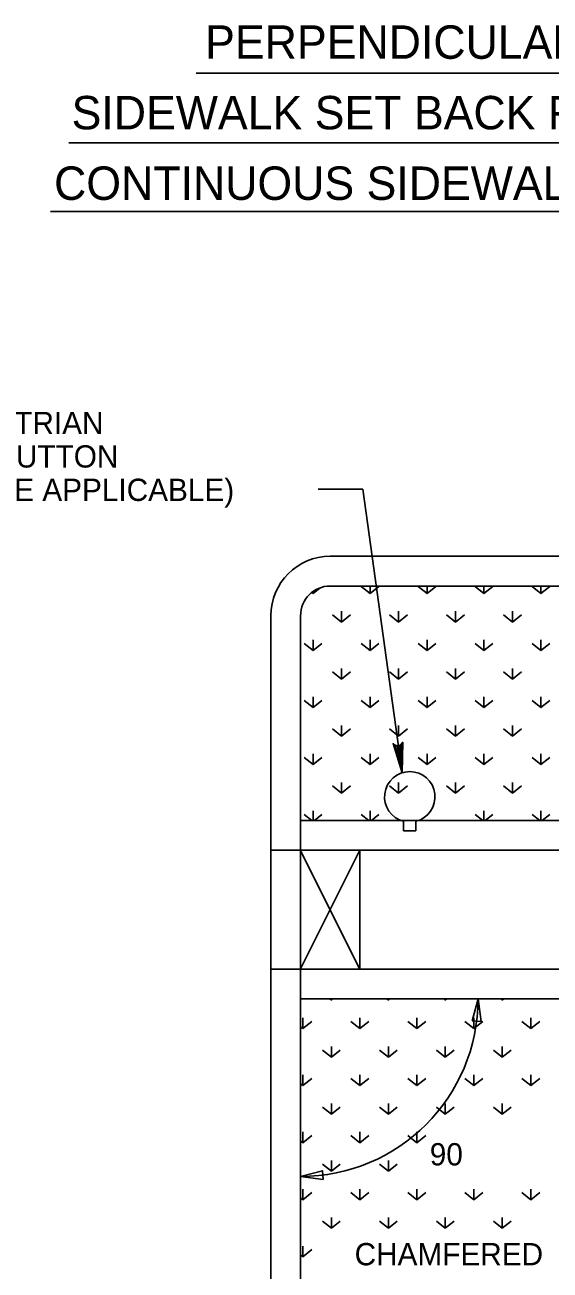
# Model space of a CAD drawing. Extents: x -344 to 940, y 22 to 1233.
# Drawn here: x 411 to 481.8, y 128.6 to 296.2 of the extents above; entities that cross this region are included whole.
import ezdxf

# ---------------------------------------------------------------- set-up
doc = ezdxf.new("R2010")
doc.units = 0
doc.layers.add('2', color=7, linetype='Continuous')
doc.layers.add('Default', color=7, linetype='Continuous')

msp = doc.modelspace()

# ---------------------------------------------------------------- linework, layer by layer
at = {"layer": '2'}
for p, q in [((434.15, 289.75), (543.1, 289.75)), ((416.96, 280.34), (561.11, 280.34)), ((414.51, 271.13), (563.16, 271.13)), ((462.1, 187.7), (462.1, 189)), ((463.75, 189), (463.75, 187.7)), ((463.75, 187.7), (462.1, 187.7)), ((456.2, 185.09), (448.14, 169.03)), ((448.19, 185.04), (456.2, 169.09))]:
    msp.add_line(p, q, dxfattribs=at)
msp.add_lwpolyline([(461.83, 199.42), (461.57, 199.24), (461.88, 195.53), (461.83, 199.42), (461.97, 199.64), (461.88, 195.53), (461.19, 199.18), (460.89, 199.28), (461.88, 195.53), (460.68, 199.46), (460.89, 199.28)], dxfattribs=at)
msp.add_arc((462.93, 192.29), 3.4, 284.1014, 255.8986, dxfattribs=at)
at = {"layer": 'Default'}
for p, q in [((456.6, 233.73), (450.6, 233.73)), ((461.88, 195.53), (456.6, 233.73)), ((452.2, 224.68), (656.79, 224.68)), ((449.89, 219.67), (449.76, 219.77)), ((449.89, 219.67), (450.82, 220.41)), ((449.89, 219.86), (449.89, 219.67)), ((452.2, 220.68), (656.79, 220.68)), ((457.57, 219.67), (456.37, 220.63)), ((457.57, 220.68), (457.57, 219.67)), ((457.57, 219.67), (458.77, 220.63)), ((465.25, 219.67), (464.05, 220.63)), ((465.25, 220.68), (465.25, 219.67)), ((465.25, 219.67), (466.45, 220.63)), ((472.93, 219.67), (471.73, 220.63)), ((472.93, 220.68), (472.93, 219.67)), ((472.93, 219.67), (474.13, 220.63)), ((480.61, 219.67), (479.41, 220.63)), ((480.61, 220.68), (480.61, 219.67)), ((480.61, 219.67), (481.81, 220.63)), ((444.2, 216.68), (444.2, 193.09)), ((448.2, 216.68), (448.2, 169.09)), ((453.73, 215.83), (452.53, 216.79)), ((453.73, 217.27), (453.73, 215.83)), ((453.73, 215.83), (454.93, 216.79)), ((461.41, 215.83), (460.21, 216.79)), ((461.41, 217.27), (461.41, 215.83)), ((461.41, 215.83), (462.61, 216.79)), ((469.09, 215.83), (467.89, 216.79)), ((469.09, 217.27), (469.09, 215.83)), ((469.09, 215.83), (470.29, 216.79)), ((476.77, 215.83), (475.57, 216.79)), ((476.77, 217.27), (476.77, 215.83)), ((476.77, 215.83), (477.97, 216.79)), ((449.89, 211.99), (448.69, 212.95)), ((449.89, 213.43), (449.89, 211.99)), ((449.89, 211.99), (451.09, 212.95)), ((457.57, 211.99), (456.37, 212.95)), ((457.57, 213.43), (457.57, 211.99)), ((457.57, 211.99), (458.77, 212.95)), ((465.25, 211.99), (464.05, 212.95)), ((465.25, 213.43), (465.25, 211.99)), ((465.25, 211.99), (466.45, 212.95)), ((472.93, 211.99), (471.73, 212.95)), ((472.93, 213.43), (472.93, 211.99)), ((472.93, 211.99), (474.13, 212.95)), ((480.61, 211.99), (479.41, 212.95)), ((480.61, 213.43), (480.61, 211.99)), ((480.61, 211.99), (481.81, 212.95)), ((453.73, 209.59), (453.73, 208.15)), ((461.41, 209.59), (461.41, 208.15)), ((469.09, 209.59), (469.09, 208.15)), ((476.77, 209.59), (476.77, 208.15)), ((453.73, 208.15), (452.53, 209.11)), ((453.73, 208.15), (454.93, 209.11)), ((461.41, 208.15), (460.21, 209.11)), ((461.41, 208.15), (462.61, 209.11)), ((469.09, 208.15), (467.89, 209.11)), ((469.09, 208.15), (470.29, 209.11)), ((476.77, 208.15), (475.57, 209.11)), ((476.77, 208.15), (477.97, 209.11)), ((449.89, 204.31), (448.69, 205.27)), ((449.89, 205.75), (449.89, 204.31)), ((449.89, 204.31), (451.09, 205.27)), ((457.57, 204.31), (456.37, 205.27)), ((457.57, 205.75), (457.57, 204.31)), ((457.57, 204.31), (458.77, 205.27)), ((465.25, 204.31), (464.05, 205.27)), ((465.25, 205.75), (465.25, 204.31)), ((465.25, 204.31), (466.45, 205.27)), ((472.93, 204.31), (471.73, 205.27)), ((472.93, 205.75), (472.93, 204.31)), ((472.93, 204.31), (474.13, 205.27)), ((480.61, 204.31), (479.41, 205.27)), ((480.61, 205.75), (480.61, 204.31)), ((480.61, 204.31), (481.81, 205.27)), ((453.73, 200.47), (452.53, 201.43)), ((453.73, 201.91), (453.73, 200.47)), ((453.73, 200.47), (454.93, 201.43)), ((461.41, 200.47), (460.21, 201.43)), ((461.41, 201.91), (461.41, 200.47)), ((461.41, 200.47), (462.61, 201.43)), ((469.09, 200.47), (467.89, 201.43)), ((469.09, 201.91), (469.09, 200.47)), ((469.09, 200.47), (470.29, 201.43)), ((476.77, 200.47), (475.57, 201.43)), ((476.77, 201.91), (476.77, 200.47)), ((476.77, 200.47), (477.97, 201.43)), ((449.89, 198.07), (449.89, 196.63)), ((457.57, 198.07), (457.57, 196.63)), ((465.25, 198.07), (465.25, 196.63)), ((472.93, 198.07), (472.93, 196.63)), ((480.61, 198.07), (480.61, 196.63)), ((449.89, 196.63), (448.69, 197.59)), ((449.89, 196.63), (451.09, 197.59)), ((457.57, 196.63), (456.37, 197.59)), ((457.57, 196.63), (458.77, 197.59)), ((465.25, 196.63), (464.05, 197.59)), ((465.25, 196.63), (466.45, 197.59)), ((472.93, 196.63), (471.73, 197.59)), ((472.93, 196.63), (474.13, 197.59)), ((480.61, 196.63), (479.41, 197.59)), ((480.61, 196.63), (481.81, 197.59)), ((444.2, 193.09), (444.2, 81.29)), ((453.73, 192.79), (452.53, 193.75)), ((453.73, 194.23), (453.73, 192.79)), ((453.73, 192.79), (454.93, 193.75)), ((461.41, 192.79), (460.21, 193.75)), ((461.41, 194.23), (461.41, 192.79)), ((461.41, 192.79), (462.61, 193.75)), ((469.09, 192.79), (467.89, 193.75)), ((469.09, 194.23), (469.09, 192.79)), ((469.09, 192.79), (470.29, 193.75)), ((476.77, 192.79), (475.57, 193.75)), ((476.77, 194.23), (476.77, 192.79)), ((476.77, 192.79), (477.97, 193.75)), ((449.72, 189.09), (448.69, 189.91)), ((449.89, 190.39), (449.89, 189.09)), ((450.07, 189.09), (451.09, 189.91)), ((457.4, 189.09), (456.37, 189.91)), ((457.57, 190.39), (457.57, 189.09)), ((457.75, 189.09), (458.77, 189.91)), ((472.76, 189.09), (471.73, 189.91)), ((472.93, 190.39), (472.93, 189.09)), ((473.11, 189.09), (474.13, 189.91)), ((480.44, 189.09), (479.41, 189.91)), ((480.61, 190.39), (480.61, 189.09)), ((480.79, 189.09), (481.81, 189.91)), ((448.2, 189.09), (507.84, 189.09)), ((444.2, 185.09), (509.49, 185.09)), ((448.2, 185.09), (448.2, 81.29)), ((456.2, 185.09), (456.2, 169.09)), ((444.2, 169.09), (514.56, 169.09)), ((448.2, 165.09), (513.58, 165.09)), ((452.36, 164.92), (452.15, 165.09)), ((452.36, 165.09), (452.36, 164.92)), ((452.36, 164.92), (452.57, 165.09)), ((460.04, 164.92), (459.83, 165.09)), ((460.04, 165.09), (460.04, 164.92)), ((460.04, 164.92), (460.25, 165.09)), ((467.72, 164.92), (467.51, 165.09)), ((467.72, 165.09), (467.72, 164.92)), ((467.72, 164.92), (467.93, 165.09)), ((475.4, 164.92), (475.19, 165.09)), ((475.4, 165.09), (475.4, 164.92)), ((475.4, 164.92), (475.61, 165.09)), ((448.52, 161.08), (448.2, 161.33)), ((448.52, 162.52), (448.52, 161.08)), ((448.52, 161.08), (449.72, 162.04)), ((456.2, 161.08), (455, 162.04)), ((456.2, 162.52), (456.2, 161.08)), ((456.2, 161.08), (457.4, 162.04)), ((463.88, 161.08), (462.68, 162.04)), ((463.88, 162.52), (463.88, 161.08)), ((463.88, 161.08), (465.08, 162.04)), ((471.56, 161.08), (470.36, 162.04)), ((471.56, 162.52), (471.56, 161.08)), ((471.56, 161.08), (472.76, 162.04)), ((479.24, 161.08), (478.04, 162.04)), ((479.24, 162.52), (479.24, 161.08)), ((479.24, 161.08), (480.44, 162.04)), ((452.36, 157.24), (451.16, 158.2)), ((452.36, 158.68), (452.36, 157.24)), ((452.36, 157.24), (453.56, 158.2)), ((460.04, 157.24), (458.84, 158.2)), ((460.04, 158.68), (460.04, 157.24)), ((460.04, 157.24), (461.24, 158.2)), ((467.72, 157.24), (466.52, 158.2)), ((467.72, 158.68), (467.72, 157.24)), ((467.72, 157.24), (468.92, 158.2)), ((475.4, 157.24), (474.2, 158.2)), ((475.4, 158.68), (475.4, 157.24)), ((475.4, 157.24), (476.6, 158.2)), ((448.52, 154.84), (448.52, 153.4)), ((448.52, 153.4), (449.72, 154.36)), ((456.2, 153.4), (455, 154.36)), ((456.2, 154.84), (456.2, 153.4)), ((456.2, 153.4), (457.4, 154.36)), ((463.88, 153.4), (462.68, 154.36)), ((463.88, 154.84), (463.88, 153.4)), ((463.88, 153.4), (465.08, 154.36)), ((471.56, 153.4), (470.36, 154.36)), ((471.56, 154.84), (471.56, 153.4)), ((471.56, 153.4), (472.76, 154.36)), ((479.24, 153.4), (478.04, 154.36)), ((479.24, 154.84), (479.24, 153.4)), ((479.24, 153.4), (480.44, 154.36)), ((448.52, 153.4), (448.2, 153.65)), ((452.36, 151), (452.36, 149.56)), ((460.04, 151), (460.04, 149.56)), ((467.72, 151), (467.72, 149.56)), ((475.4, 151), (475.4, 149.56)), ((452.36, 149.56), (451.16, 150.52)), ((452.36, 149.56), (453.56, 150.52)), ((460.04, 149.56), (458.84, 150.52)), ((460.04, 149.56), (461.24, 150.52)), ((467.72, 149.56), (466.52, 150.52)), ((467.72, 149.56), (468.92, 150.52)), ((475.4, 149.56), (474.2, 150.52)), ((475.4, 149.56), (476.6, 150.52)), ((448.52, 145.72), (448.2, 145.97)), ((448.52, 147.16), (448.52, 145.72)), ((448.52, 145.72), (449.72, 146.68)), ((456.2, 145.72), (455, 146.68)), ((456.2, 147.16), (456.2, 145.72)), ((456.2, 145.72), (457.4, 146.68)), ((463.88, 145.72), (462.68, 146.68)), ((463.88, 147.16), (463.88, 145.72)), ((463.88, 145.72), (465.08, 146.68)), ((452.36, 141.88), (451.16, 142.84)), ((452.36, 143.32), (452.36, 141.88)), ((452.36, 141.88), (453.56, 142.84)), ((460.04, 141.88), (458.84, 142.84)), ((460.04, 143.32), (460.04, 141.88)), ((460.04, 141.88), (461.24, 142.84)), ((448.52, 139.48), (448.52, 138.04)), ((456.2, 139.48), (456.2, 138.04)), ((463.88, 139.48), (463.88, 138.04)), ((471.56, 139.48), (471.56, 138.04)), ((479.24, 139.48), (479.24, 138.04)), ((448.52, 138.04), (448.2, 138.29)), ((448.52, 138.04), (449.72, 139)), ((456.2, 138.04), (455, 139)), ((456.2, 138.04), (457.4, 139)), ((463.88, 138.04), (462.68, 139)), ((463.88, 138.04), (465.08, 139)), ((471.56, 138.04), (470.36, 139)), ((471.56, 138.04), (472.76, 139)), ((479.24, 138.04), (478.04, 139)), ((479.24, 138.04), (480.44, 139)), ((452.36, 134.2), (451.16, 135.16)), ((452.36, 135.64), (452.36, 134.2)), ((452.36, 134.2), (453.56, 135.16)), ((460.04, 134.2), (458.84, 135.16)), ((460.04, 135.64), (460.04, 134.2)), ((460.04, 134.2), (461.24, 135.16)), ((467.72, 134.2), (466.52, 135.16)), ((467.72, 135.64), (467.72, 134.2)), ((467.72, 134.2), (468.92, 135.16)), ((475.4, 134.2), (474.2, 135.16)), ((475.4, 135.64), (475.4, 134.2)), ((475.4, 134.2), (476.6, 135.16)), ((448.52, 131.8), (448.52, 130.36)), ((448.52, 130.36), (449.72, 131.32)), ((448.52, 130.36), (448.2, 130.61))]:
    msp.add_line(p, q, dxfattribs=at)
for points in [[(471.35, 162.13), (472.14, 165.09), (472.55, 162.06)], [(451.24, 140.75), (448.2, 141.16), (451.16, 141.94)]]:
    msp.add_lwpolyline(points, close=True, dxfattribs=at)
for centre, radius, start, end in [((452.2, 216.68), 8, 90, 180), ((452.2, 216.68), 4, 90, 180), ((753.46, -151.64), 376.8, 122.5261, 142.2884), ((448.2, 165.09), 23.93, 270, 0), ((753.46, -151.64), 372.8, 124.6158, 142.2884)]:
    msp.add_arc(centre, radius, start, end, dxfattribs=at)

# ---------------------------------------------------------------- texts
at = {"layer": '2'}
for s, p in [('PERPENDICULAR RAMPS WITH', (435.34, 291.67)), ('SIDEWALK SET BACK FROM ROAD WITH', (417.34, 282.17)), ('CONTINUOUS SIDEWALK BETWEEN RAMPS', (414.98, 272.67))]:
    msp.add_text(s, height=4.5, dxfattribs=at).set_placement(p)
at = {"layer": 'Default'}
for s, p in [('PEDESTRIAN', (396.01, 241.13)), ('PUSHBUTTON', (396.01, 236.63)), ('(WHERE APPLICABLE)', (396.01, 232.13)), ('90', (465.62, 142.66)), ('CHAMFERED', (455.49, 129.21))]:
    msp.add_text(s, height=3, dxfattribs=at).set_placement(p)

doc.saveas('drawing.dxf')
